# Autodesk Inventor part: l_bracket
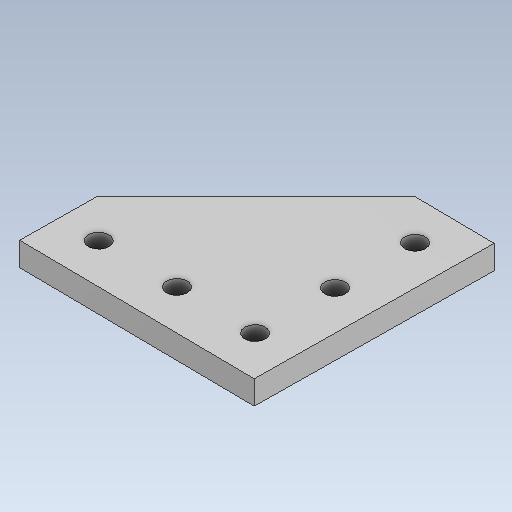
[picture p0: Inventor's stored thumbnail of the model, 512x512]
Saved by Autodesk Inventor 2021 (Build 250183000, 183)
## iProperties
Created: 2026-10
Part Number: l_bracket
Material: Generic
Document SubType Name: Modeling
Designer: hp
Density: 1 g/cm^3
Appearance: Default
Author: hp
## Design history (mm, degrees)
feature "Body1"
body "Solid1"
